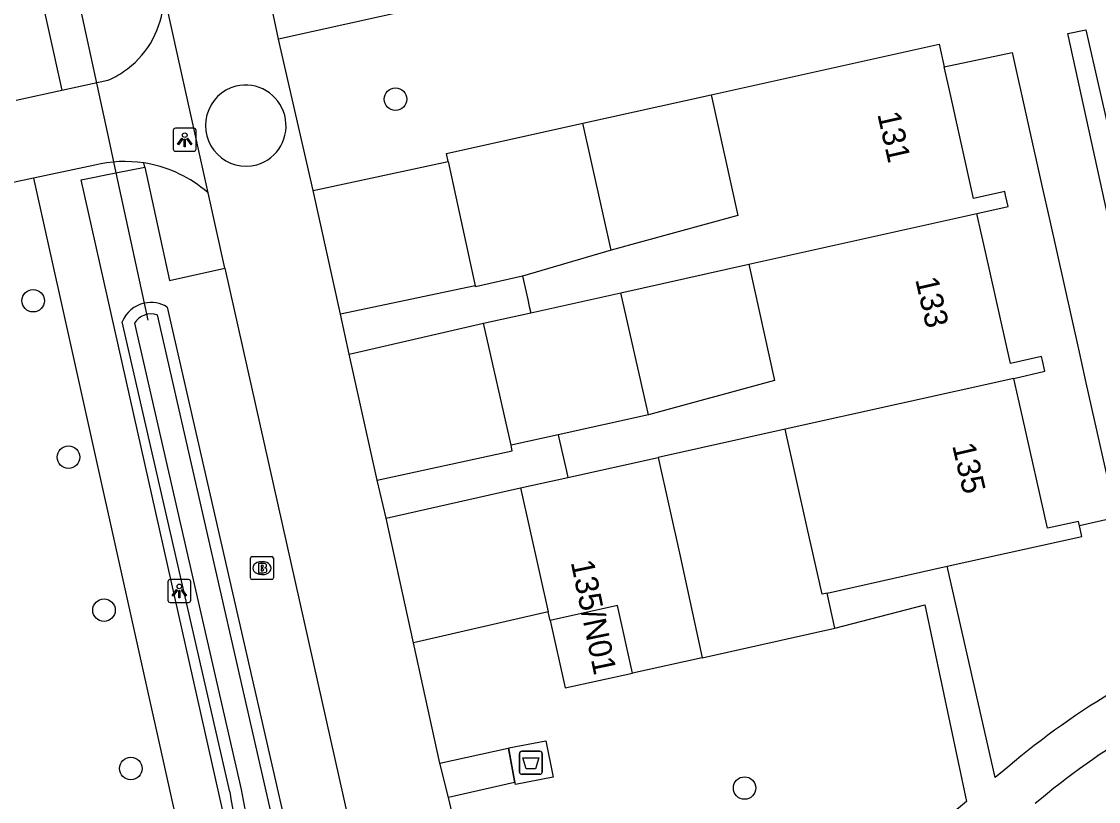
# Model space of a CAD drawing. Extents: x 156664 to 157568, y 383571 to 384421.
# Drawn here: x 156793.83 to 156840.66, y 383910.26 to 383944.18 of the extents above; entities that cross this region are included whole.
import ezdxf

# ---------------------------------------------------------------- set-up
doc = ezdxf.new("R2010")
doc.units = 0
for name, color, linetype in [('IMGEO_Afval_apart_plaats', 7, 'Continuous'), ('IMGEO_Berm_groen', 7, 'Continuous'), ('IMGEO_Boom', 7, 'Continuous'), ('IMGEO_Brandkraan', 7, 'Continuous'), ('IMGEO_Duiker', 7, 'Continuous'), ('IMGEO_Groenvoorziening', 7, 'Continuous'), ('IMGEO_Haag', 7, 'Continuous'), ('IMGEO_Lichtpunt', 7, 'Continuous'), ('IMGEO_Muur', 7, 'Continuous'), ('IMGEO_Pand', 7, 'Continuous'), ('IMGEO_Pand_nummerreeks', 7, 'Continuous'), ('IMGEO_Parkeervlak_halfverhard', 7, 'Continuous'), ('IMGEO_Parkeervlak_open', 7, 'Continuous'), ('IMGEO_Rijbaan_lokaal_gesloten', 7, 'Continuous'), ('IMGEO_Rijbaan_lokaal_open', 7, 'Continuous'), ('IMGEO_Voetpad_gesloten', 7, 'Continuous'), ('IMGEO_Voetpad_open', 7, 'Continuous'), ('IMGEO_Waterloop', 7, 'Continuous')]:
    doc.layers.add(name, color=color, linetype=linetype)

msp = doc.modelspace()

# ---------------------------------------------------------------- linework, layer by layer
at = {"layer": 'IMGEO_Afval_apart_plaats'}
for p, q in [((156815.482, 383911.541), (156815.482, 383912.341)), ((156815.482, 383912.341), (156815.482, 383911.541)), ((156815.582, 383912.441), (156816.372, 383912.441)), ((156816.372, 383912.441), (156815.582, 383912.441)), ((156816.472, 383912.341), (156816.472, 383911.541)), ((156816.472, 383911.541), (156816.472, 383912.341)), ((156816.372, 383911.441), (156815.582, 383911.441)), ((156815.582, 383911.441), (156816.372, 383911.441))]:
    msp.add_line(p, q, dxfattribs=at)
msp.add_lwpolyline([(156815.625, 383912.155), (156816.329, 383912.155), (156816.18, 383911.685), (156815.774, 383911.685), (156815.625, 383912.155)], dxfattribs=at)
for centre, start, end in [((156815.582, 383912.341), 90, 180), ((156815.582, 383912.341), 90, 180), ((156816.372, 383912.341), 0, 90), ((156816.372, 383912.341), 360, 90), ((156815.582, 383911.541), 180, 270), ((156815.582, 383911.541), 180, 270), ((156816.372, 383911.541), 270, 0), ((156816.372, 383911.541), 270, 0)]:
    msp.add_arc(centre, 0.1, start, end, dxfattribs=at)
at = {"layer": 'IMGEO_Berm_groen'}
for points in [[(156800.168, 383931.757), (156806.348, 383904.688)], [(156802.886, 383910.681), (156798.212, 383931.119)]]:
    msp.add_lwpolyline(points, dxfattribs=at)
for centre, radius, start, end in [((156799.458, 383930.612), 1.346, 102.64, 157.8651), ((156799.461, 383930.617), 1.342, 58.2085, 102.7929), ((156830.582, 383915.192), 28.061, 189.251, 199.5395)]:
    msp.add_arc(centre, radius, start, end, dxfattribs=at)
at = {"layer": 'IMGEO_Boom'}
for centre in [(156810.09, 383940.8), (156794.335, 383932.037), (156795.875, 383925.235), (156797.417, 383918.579), (156798.582, 383911.692), (156825.273, 383910.845)]:
    msp.add_circle(centre, 0.489, dxfattribs=at)
at = {"layer": 'IMGEO_Brandkraan'}
for p, q in [((156803.784, 383919.982), (156803.784, 383920.834)), ((156803.859, 383920.908), (156804.711, 383920.908)), ((156804.272, 383920.688), (156804.297, 383920.688)), ((156804.785, 383920.834), (156804.785, 383919.982)), ((156804.711, 383919.908), (156803.859, 383919.908)), ((156804.295, 383920.128), (156804.27, 383920.128))]:
    msp.add_line(p, q, dxfattribs=at)
for points in [[(156803.784, 383919.982), (156803.784, 383920.834)], [(156803.859, 383920.908), (156804.711, 383920.908)], [(156804.785, 383920.834), (156804.785, 383919.982)], [(156804.132, 383920.608), (156804.132, 383920.208), (156804.345, 383920.208)], [(156804.363, 383920.608), (156804.132, 383920.608)], [(156804.311, 383920.527), (156804.257, 383920.527), (156804.257, 383920.451)], [(156804.257, 383920.451), (156804.31, 383920.451)], [(156804.319, 383920.375), (156804.257, 383920.375), (156804.257, 383920.294)], [(156804.257, 383920.294), (156804.319, 383920.294)], [(156804.711, 383919.908), (156803.859, 383919.908)]]:
    msp.add_lwpolyline(points, dxfattribs=at)
for centre, radius, start, end in [((156803.861, 383920.832), 0.0765, 91.552, 178.448), ((156803.861, 383920.832), 0.0765, 91.552, 178.448), ((156804.709, 383920.832), 0.0765, 1.552, 88.448), ((156804.709, 383920.832), 0.0765, 1.552, 88.448), ((156804.312, 383920.489), 0.0379, 267.8285, 90.9355), ((156804.32, 383920.334), 0.0404, 269.8759, 90.5077), ((156804.351, 383920.459), 0.251, 268.6676, 293.5347), ((156804.367, 383920.463), 0.145, 59.4692, 91.5367), ((156804.392, 383920.51), 0.0922, 285.5137, 58.1501), ((156804.397, 383920.318), 0.105, 301.3115, 78.989), ((156803.861, 383919.984), 0.0765, 181.552, 268.448), ((156803.861, 383919.984), 0.0765, 181.552, 268.448), ((156804.709, 383919.984), 0.0765, 271.552, 358.448), ((156804.709, 383919.984), 0.0765, 271.552, 358.448)]:
    msp.add_arc(centre, radius, start, end, dxfattribs=at)
for centre, major_axis, ratio, start_param, end_param in [((156804.271, 383920.408), (-0.387, 0.002), 0.722429, 4.712389, 7.853982), ((156804.296, 383920.408), (-0.39, 0.002), 0.717154, 1.570796, 4.712389)]:
    msp.add_ellipse(centre, major_axis=major_axis, ratio=ratio, start_param=start_param, end_param=end_param, dxfattribs=at)
at = {"layer": 'IMGEO_Duiker'}
msp.add_lwpolyline([(156796.083, 383946.154), (156796.25, 383945.383), (156797.626, 383939.03), (156797.937, 383937.594), (156799.164, 383931.925), (156799.323, 383931.192)], dxfattribs=at)
at = {"layer": 'IMGEO_Groenvoorziening'}
for points in [[(156833.955, 383942.205), (156836.909, 383942.836), (156838.218, 383936.976), (156838.514, 383935.647), (156839.821, 383929.794), (156840.117, 383928.468), (156841.425, 383922.608), (156839.83, 383922.252)], [(156818.242, 383939.753), (156823.818, 383940.987)], [(156823.434, 383916.512), (156829.202, 383917.794)]]:
    msp.add_lwpolyline(points, dxfattribs=at)
at = {"layer": 'IMGEO_Haag'}
msp.add_lwpolyline([(156840.106, 383943.823), (156843.226, 383930.161), (156844.675, 383923.242), (156843.829, 383923.092), (156839.33, 383943.662), (156840.106, 383943.823)], dxfattribs=at)
at = {"layer": 'IMGEO_Lichtpunt'}
for p, q in [((156800.428, 383939.44), (156800.428, 383938.633)), ((156800.428, 383939.44), (156800.428, 383938.633)), ((156801.33, 383939.535), (156800.522, 383939.535)), ((156801.33, 383939.535), (156800.522, 383939.535)), ((156801.424, 383938.633), (156801.424, 383939.44)), ((156801.424, 383938.633), (156801.424, 383939.44)), ((156800.522, 383938.539), (156801.33, 383938.539)), ((156800.522, 383938.539), (156801.33, 383938.539)), ((156800.194, 383919.815), (156800.194, 383919.008)), ((156800.194, 383919.815), (156800.194, 383919.008)), ((156801.096, 383919.91), (156800.288, 383919.91)), ((156801.096, 383919.91), (156800.288, 383919.91)), ((156801.19, 383919.008), (156801.19, 383919.815)), ((156801.19, 383919.008), (156801.19, 383919.815)), ((156800.288, 383918.914), (156801.096, 383918.914)), ((156800.288, 383918.914), (156801.096, 383918.914))]:
    msp.add_line(p, q, dxfattribs=at)
for points in [[(156800.802, 383939.104), (156800.841, 383939.076), (156800.653, 383938.814), (156800.615, 383938.841), (156800.802, 383939.104)], [(156800.904, 383939.056), (156800.951, 383939.056), (156800.951, 383938.734), (156800.904, 383938.734), (156800.904, 383939.056)], [(156801.014, 383939.076), (156801.052, 383939.103), (156801.239, 383938.841), (156801.2, 383938.813), (156801.014, 383939.076)], [(156800.568, 383919.479), (156800.607, 383919.451), (156800.419, 383919.189), (156800.381, 383919.216), (156800.568, 383919.479)], [(156800.67, 383919.431), (156800.717, 383919.431), (156800.717, 383919.109), (156800.67, 383919.109), (156800.67, 383919.431)], [(156800.78, 383919.451), (156800.818, 383919.478), (156801.005, 383919.216), (156800.966, 383919.188), (156800.78, 383919.451)]]:
    msp.add_lwpolyline(points, dxfattribs=at)
for centre in [(156800.927, 383939.238), (156800.693, 383919.613)]:
    msp.add_circle(centre, 0.0994, dxfattribs=at)
for centre, start, end in [((156800.522, 383939.44), 90, 180), ((156800.522, 383939.44), 90, 180), ((156801.33, 383939.44), 0, 90), ((156801.33, 383939.44), 0, 90), ((156800.522, 383938.633), 180, 270), ((156800.522, 383938.633), 180, 270), ((156801.33, 383938.633), 270, 0), ((156801.33, 383938.633), 270, 360), ((156800.288, 383919.815), 90, 180), ((156800.288, 383919.815), 90, 180), ((156801.096, 383919.815), 0, 90), ((156801.096, 383919.815), 0, 90), ((156800.288, 383919.008), 180, 270), ((156800.288, 383919.008), 180, 270), ((156801.096, 383919.008), 270, 0), ((156801.096, 383919.008), 270, 360)]:
    msp.add_arc(centre, 0.0946, start, end, dxfattribs=at)
at = {"layer": 'IMGEO_Muur'}
for points in [[(156833.955, 383942.205), (156836.909, 383942.836), (156838.218, 383936.976)], [(156818.242, 383939.753), (156823.818, 383940.987)], [(156838.514, 383935.647), (156839.821, 383929.794)], [(156840.117, 383928.468), (156841.425, 383922.608), (156839.83, 383922.252)], [(156829.202, 383917.794), (156828.862, 383919.324)], [(156823.434, 383916.512), (156829.202, 383917.794)]]:
    msp.add_lwpolyline(points, dxfattribs=at)
at = {"layer": 'IMGEO_Pand'}
for points in [[(156823.818, 383940.987), (156833.736, 383943.193), (156833.955, 383942.205)], [(156835.377, 383935.827), (156836.733, 383936.134), (156836.622, 383936.62), (156836.586, 383936.783), (156835.23, 383936.476), (156834.15, 383941.33), (156833.955, 383942.205)], [(156823.818, 383940.987), (156824.985, 383935.745), (156819.469, 383934.238)], [(156812.384, 383938.086), (156812.309, 383938.432), (156818.242, 383939.753)], [(156819.469, 383934.238), (156818.242, 383939.753)], [(156812.384, 383938.086), (156813.553, 383932.69)], [(156825.454, 383933.622), (156835.377, 383935.827)], [(156836.979, 383928.659), (156838.333, 383928.97), (156838.226, 383929.438), (156838.186, 383929.613), (156836.831, 383929.302), (156835.747, 383934.165), (156835.564, 383934.988), (156835.377, 383935.827)], [(156819.469, 383934.238), (156815.612, 383933.105)], [(156819.89, 383932.386), (156825.454, 383933.622)], [(156825.454, 383933.622), (156826.57, 383928.572), (156821.097, 383927.076)], [(156815.612, 383933.105), (156813.564, 383932.64), (156813.553, 383932.69)], [(156815.612, 383933.105), (156815.84, 383932.096), (156815.91, 383931.788), (156815.972, 383931.515)], [(156815.972, 383931.515), (156819.89, 383932.386)], [(156821.097, 383927.076), (156819.89, 383932.386)], [(156813.922, 383931.06), (156815.972, 383931.515)], [(156815.119, 383925.748), (156813.922, 383931.06)], [(156836.979, 383928.659), (156827.04, 383926.444)], [(156839.83, 383922.252), (156839.787, 383922.442), (156838.44, 383922.142), (156837.355, 383926.98), (156837.169, 383927.81), (156836.979, 383928.659)], [(156821.097, 383927.076), (156817.17, 383926.204)], [(156827.04, 383926.444), (156821.518, 383925.224)], [(156828.862, 383919.324), (156828.648, 383919.276), (156828, 383922.163), (156827.04, 383926.444)], [(156817.17, 383926.204), (156815.119, 383925.748)], [(156817.17, 383926.204), (156817.228, 383925.944), (156817.522, 383924.626), (156817.584, 383924.35)], [(156817.584, 383924.35), (156821.518, 383925.224)], [(156821.518, 383925.224), (156822.464, 383920.921), (156823.434, 383916.512)], [(156815.534, 383923.894), (156817.584, 383924.35)], [(156815.534, 383923.894), (156816.732, 383918.51)], [(156834.083, 383920.486), (156839.933, 383921.788), (156839.83, 383922.252)], [(156828.862, 383919.324), (156834.083, 383920.486)], [(156820.398, 383915.844), (156819.745, 383918.78), (156816.817, 383918.128)], [(156816.817, 383918.128), (156816.732, 383918.51)], [(156816.817, 383918.128), (156817.468, 383915.2), (156820.398, 383915.844)], [(156823.434, 383916.512), (156820.398, 383915.844)]]:
    msp.add_lwpolyline(points, dxfattribs=at)
at = {"layer": 'IMGEO_Parkeervlak_halfverhard'}
msp.add_lwpolyline([(156799.187, 383937.84), (156800.265, 383932.911), (156802.676, 383933.449)], dxfattribs=at)
at = {"layer": 'IMGEO_Parkeervlak_open'}
for points in [[(156806.516, 383936.828), (156812.384, 383938.086)], [(156816.732, 383918.51), (156810.873, 383917.164)]]:
    msp.add_lwpolyline(points, dxfattribs=at)
at = {"layer": 'IMGEO_Rijbaan_lokaal_gesloten'}
for points in [[(156801.949, 383936.722), (156800.028, 383945.365)], [(156795.59, 383941.189), (156797.583, 383941.621)], [(156793.6, 383940.758), (156795.59, 383941.189)], [(156797.015, 383937.936), (156794.353, 383937.37)], [(156794.353, 383937.37), (156783.169, 383934.99), (156784.232, 383930.211), (156784.555, 383928.753)], [(156801.949, 383936.722), (156801.775, 383936.87)]]:
    msp.add_lwpolyline(points, dxfattribs=at)
for centre, radius, start, end in [((156796.012, 383945.301), 4.001, 304.3465, 353.1493), ((156796.056, 383945.213), 3.903, 293.0369, 304.5462), ((156798.314, 383932.576), 5.515, 81.3224, 103.6217), ((156798.31, 383932.566), 5.525, 51.1604, 81.2954)]:
    msp.add_arc(centre, radius, start, end, dxfattribs=at)
at = {"layer": 'IMGEO_Rijbaan_lokaal_open'}
for points in [[(156805.002, 383943.411), (156804.664, 383944.993)], [(156806.516, 383936.828), (156805.002, 383943.411)], [(156802.676, 383933.449), (156801.949, 383936.722)], [(156807.701, 383931.447), (156806.516, 383936.828)], [(156802.676, 383933.449), (156808.224, 383908.678)], [(156808.084, 383929.719), (156807.701, 383931.447)], [(156809.293, 383924.239), (156808.084, 383929.719)], [(156809.69, 383922.576), (156809.293, 383924.239)], [(156810.873, 383917.164), (156809.69, 383922.576)], [(156812.023, 383911.93), (156810.873, 383917.164)], [(156812.396, 383910.435), (156812.023, 383911.93)], [(156812.552, 383909.758), (156812.396, 383910.435)]]:
    msp.add_lwpolyline(points, dxfattribs=at)
for centre, radius, start, end in [((156803.601, 383939.654), 1.772, 104.6402, 285.0477), ((156803.56, 383939.644), 1.773, 286.4018, 103.2861), ((156857.829, 383887.006), 27.403, 113.6815, 132.2773)]:
    msp.add_arc(centre, radius, start, end, dxfattribs=at)
at = {"layer": 'IMGEO_Voetpad_gesloten'}
msp.add_lwpolyline([(156815.303, 383910.995), (156815.026, 383912.59), (156816.636, 383912.903), (156816.942, 383911.31), (156815.303, 383910.995)], dxfattribs=at)
at = {"layer": 'IMGEO_Voetpad_open'}
for points in [[(156789.615, 383980.975), (156788.201, 383980.63), (156786.905, 383980.313), (156795.59, 383941.189)], [(156810.91, 383944.714), (156805.002, 383943.411)], [(156799.187, 383937.84), (156799.146, 383938.028)], [(156803.985, 383904.226), (156803.42, 383906.092), (156796.429, 383937.298), (156797.937, 383937.594), (156799.187, 383937.84)], [(156794.353, 383937.37), (156800.623, 383909.14), (156795.088, 383907.896), (156795.487, 383906.115), (156801.01, 383907.365)], [(156813.553, 383932.69), (156807.701, 383931.447)], [(156808.084, 383929.719), (156813.922, 383931.06)], [(156809.293, 383924.239), (156815.172, 383925.514), (156815.119, 383925.748)], [(156809.69, 383922.576), (156815.534, 383923.894)], [(156836.719, 383911.755), (156836.167, 383911.298), (156834.083, 383920.486)], [(156829.202, 383917.794), (156828.862, 383919.324)], [(156829.202, 383917.794), (156833.107, 383918.804), (156834.922, 383910.265), (156820.131, 383898.001)], [(156812.023, 383911.93), (156814.996, 383912.584), (156815.273, 383911.078), (156812.396, 383910.435)]]:
    msp.add_lwpolyline(points, dxfattribs=at)
for centre, radius, start, end in [((156858.538, 383886.116), 33.666, 110.2755, 130.3972), ((156858.999, 383885.284), 32.616, 110.6169, 130.2839)]:
    msp.add_arc(centre, radius, start, end, dxfattribs=at)
at = {"layer": 'IMGEO_Waterloop'}
for points in [[(156798.736, 383931.057), (156803.374, 383910.776), (156803.688, 383909.152), (156804.098, 383907.549), (156804.605, 383905.974), (156806.222, 383902.054), (156808.205, 383898.305), (156810.535, 383894.762), (156810.777, 383894.483)], [(156811.151, 383895.035), (156809.099, 383898.036), (156807.334, 383901.215), (156805.872, 383904.543), (156799.737, 383931.416)]]:
    msp.add_lwpolyline(points, dxfattribs=at)
msp.add_arc((156799.461, 383930.61), 0.851, 71.088, 148.3719, dxfattribs=at)

# ---------------------------------------------------------------- texts
at = {"layer": 'IMGEO_Pand_nummerreeks'}
for s, rotation, p in [('131', 282.7767, (156831.039, 383940.152)), ('133', 282.9143, (156832.689, 383932.961)), ('135', 283.0575, (156834.293, 383925.743)), ('135/N01', 281.7344, (156817.71, 383920.665))]:
    msp.add_text(s, height=1, rotation=rotation, dxfattribs=at).set_placement(p)

doc.saveas('drawing.dxf')
